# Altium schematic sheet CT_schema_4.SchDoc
size 522 x 483 mm
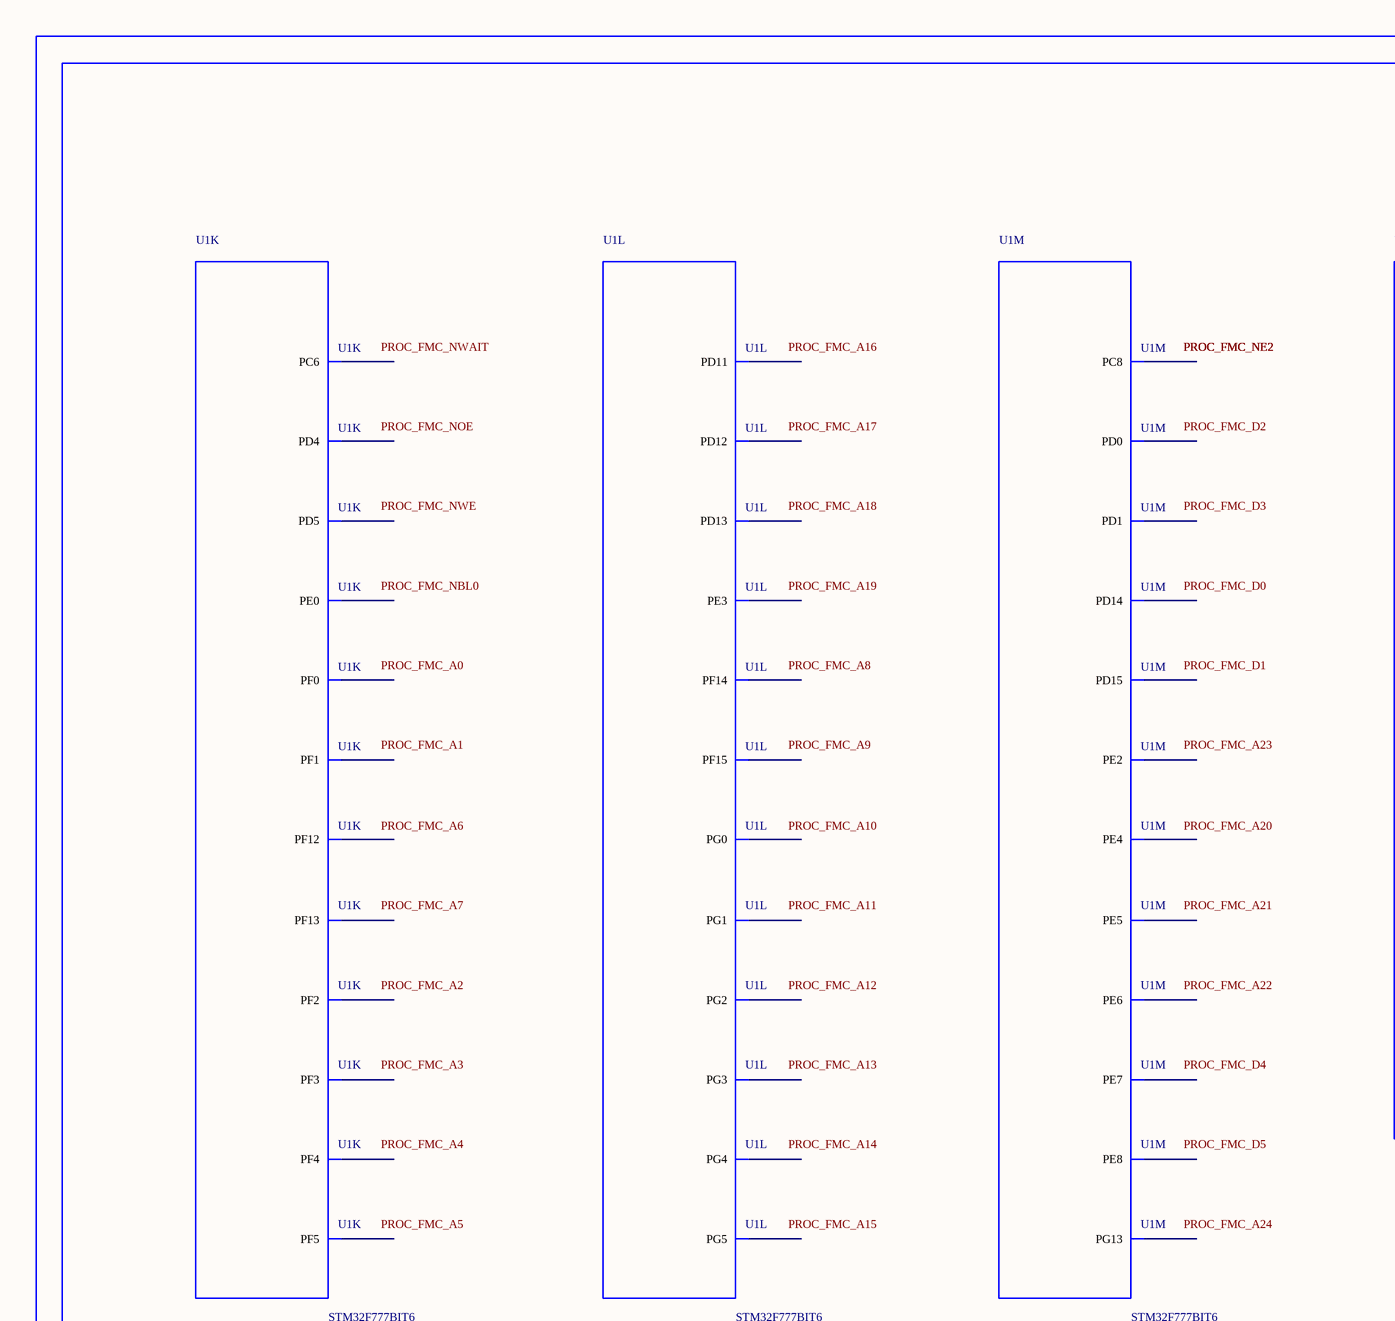
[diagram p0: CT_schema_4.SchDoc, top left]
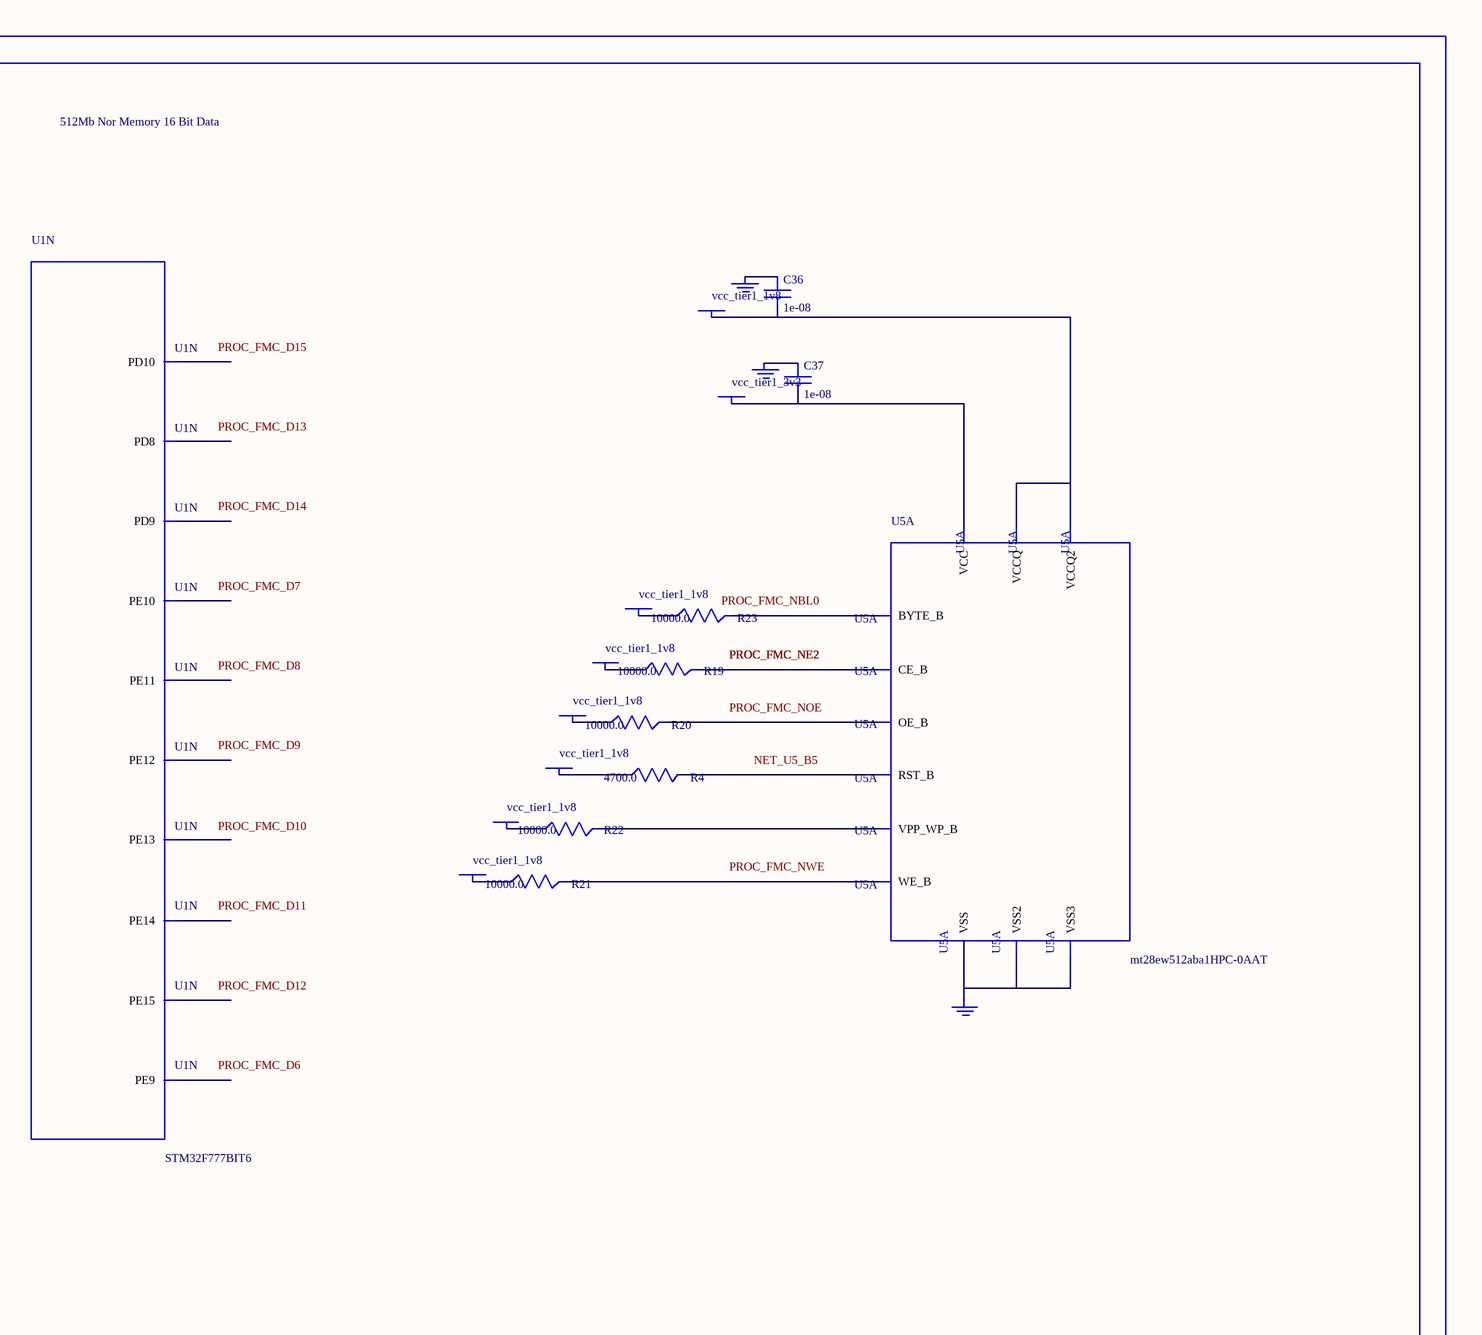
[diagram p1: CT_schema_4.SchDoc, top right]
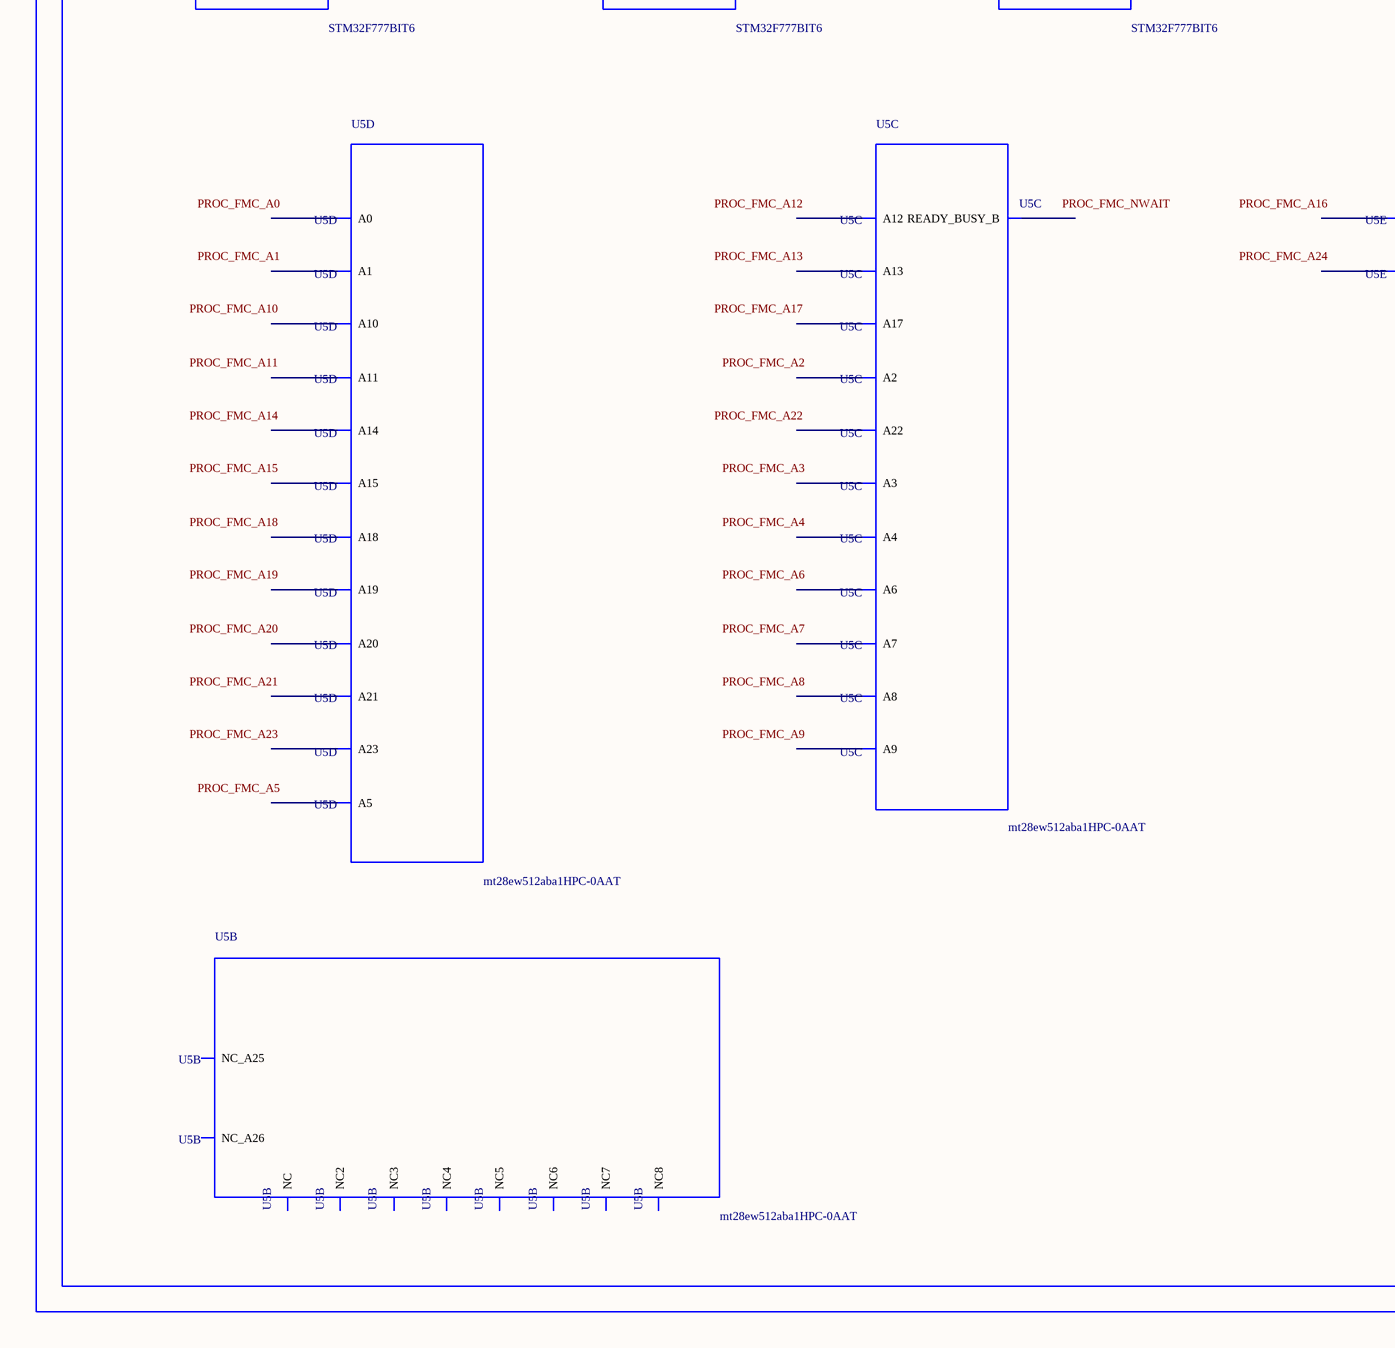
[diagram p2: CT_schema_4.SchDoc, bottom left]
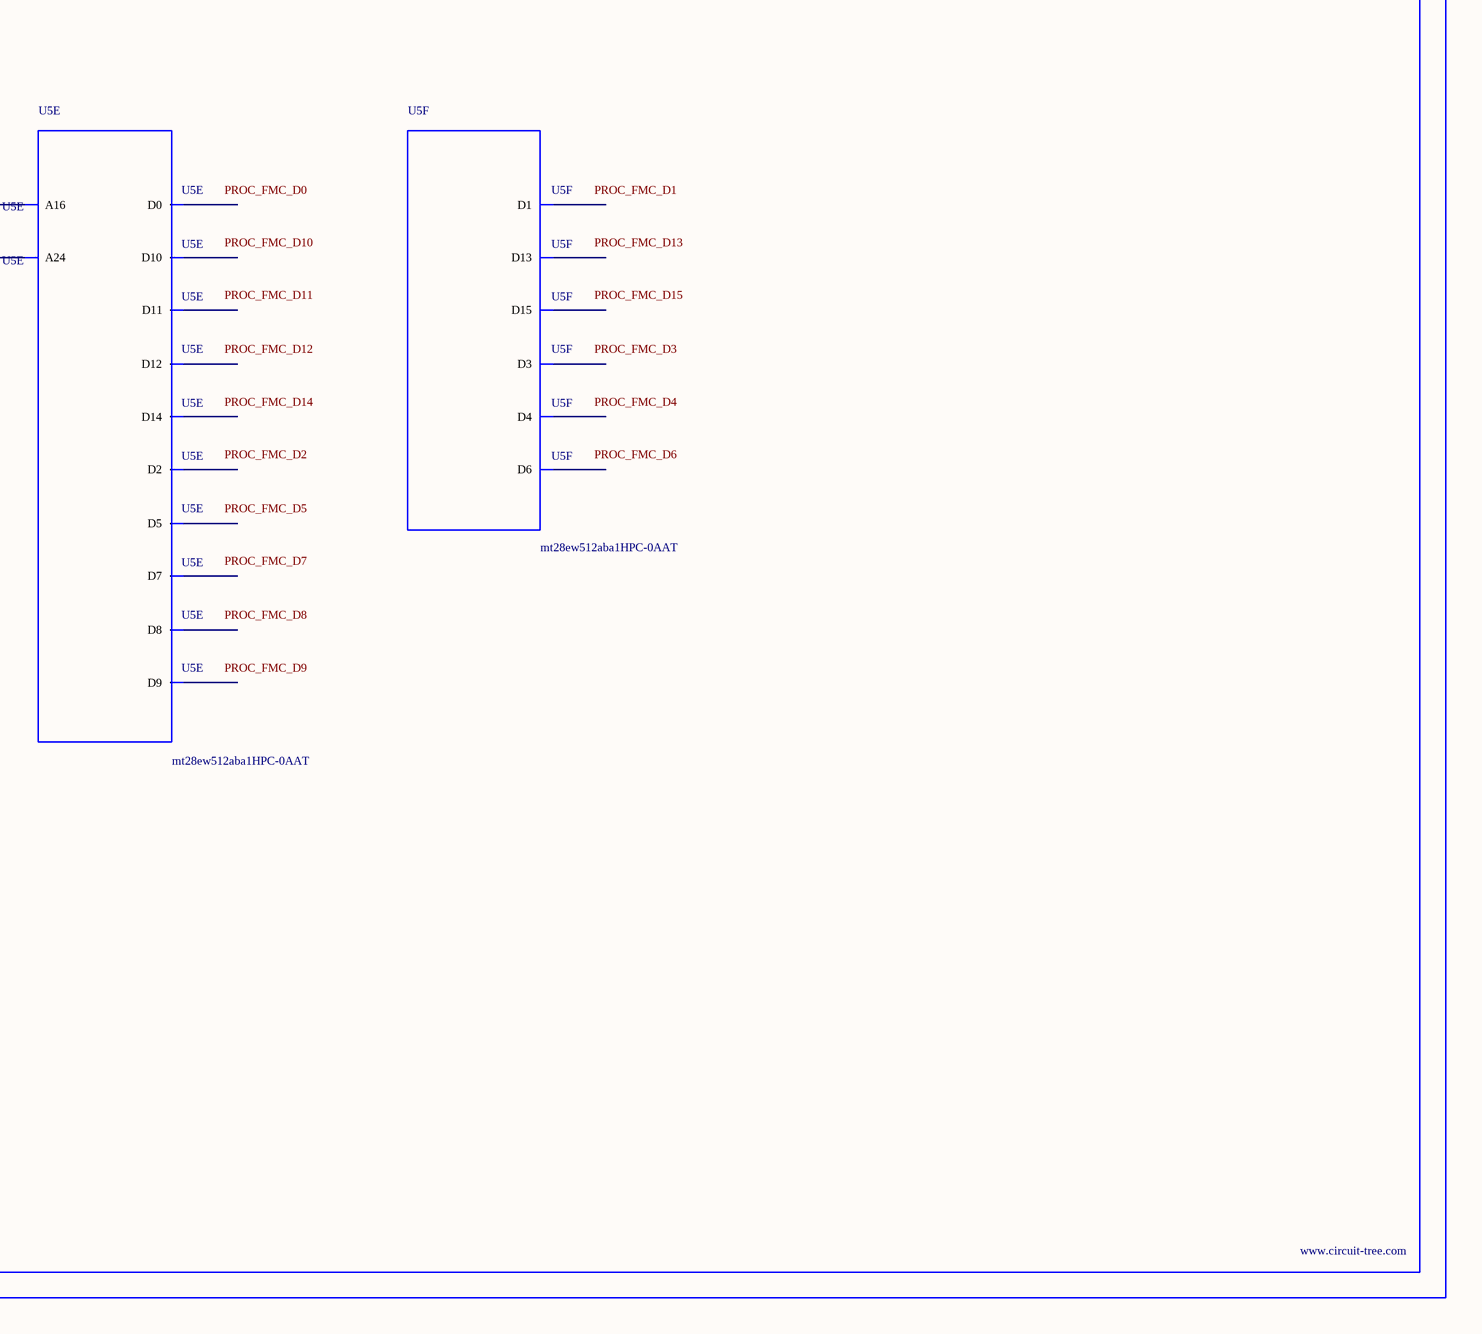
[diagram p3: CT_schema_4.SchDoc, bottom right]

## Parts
BORDER3  (no value)
C36  1e-08  [C0402]
C37  1e-08  [C0402]
GND_INSTANCE_3_0  (no value)
GND_INSTANCE_3_1  (no value)
GND_INSTANCE_3_2  (no value)
POWER_INSTANCE_3_0  vcc_tier1_1v8
POWER_INSTANCE_3_1  vcc_tier1_3v3
POWER_INSTANCE_3_2  vcc_tier1_1v8
POWER_INSTANCE_3_3  vcc_tier1_1v8
POWER_INSTANCE_3_4  vcc_tier1_1v8
POWER_INSTANCE_3_5  vcc_tier1_1v8
POWER_INSTANCE_3_6  vcc_tier1_1v8
POWER_INSTANCE_3_7  vcc_tier1_1v8
R4  4700.0  [R0603]
R19  10000.0  [R0603]
R20  10000.0  [R0603]
R21  10000.0  [R0603]
R22  10000.0  [R0603]
R23  10000.0  [R0603]
U1  STM32F777BIT6  [LQFP208]  (parts K,L,M,N of 15)
U5  mt28ew512aba1HPC-0AAT  [LBGA-64]  (parts A,B,C,D,E,F of 6)

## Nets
NetC36_1: C36.1 GND_INSTANCE_3_0.0(GND)
NetC36_2: C36.2 POWER_INSTANCE_3_0.0(PWR) U5.D8(VCCQ) U5.F1(VCCQ2)
NetC37_1: C37.1 GND_INSTANCE_3_1.0(GND)
NetC37_2: C37.2 POWER_INSTANCE_3_1.0(PWR) U5.G5(VCC)
NetGND_INSTANCE_3_2_0: GND_INSTANCE_3_2.0(GND) U5.E8(VSS) U5.H2(VSS2) U5.H7(VSS3)
NetPOWER_INSTANCE_3_2_0: POWER_INSTANCE_3_2.0(PWR) R19.1
NetPOWER_INSTANCE_3_3_0: POWER_INSTANCE_3_3.0(PWR) R20.1
NetPOWER_INSTANCE_3_4_0: POWER_INSTANCE_3_4.0(PWR) R21.1
NetPOWER_INSTANCE_3_5_0: POWER_INSTANCE_3_5.0(PWR) R22.1
NetPOWER_INSTANCE_3_6_0: POWER_INSTANCE_3_6.0(PWR) R23.1
NetPOWER_INSTANCE_3_7_0: POWER_INSTANCE_3_7.0(PWR) R4.1
NetR4_2: R4.2 U5.B5(RST_B)
NetR19_2: R19.2 U5.F2(CE_B)
NetR20_2: R20.2 U5.G2(OE_B)
NetR21_2: R21.2 U5.A5(WE_B)
NetR22_2: R22.2 U5.B4(VPP_WP_B)
NetR23_2: R23.2 U5.F7(BYTE_B)

Not connected (* = marked no-connect by the designer): U1 1(PE2) 2(PE3) 3(PE4) 4(PE5) 5(PE6) 16(PF0) 17(PF1) 18(PF2) 22(PF3) 23(PF4) 24(PF5) 71(PF12) 74(PF13) 75(PF14) 76(PF15) 77(PG0) 78(PG1) 79(PE7) 80(PE8) 81(PE9) 84(PE10) 85(PE11) 86(PE12) 87(PE13) 88(PE14) 89(PE15) 108(PD8) 109(PD9) 110(PD10) 111(PD11) 112(PD12) 113(PD13) 116(PD14) 117(PD15) 129(PG2) 130(PG3) 131(PG4) 132(PG5) 138(PC6) 140(PC8) 164(PD0) 165(PD1) 168(PD4) 169(PD5) 182(PG13) 200(PE0); U5 A1(NC) A2(A3) A3(A7) A4(READY_BUSY_B) A6(A9) A7(A13) A8(NC2) B1(NC_A26) B2(A4) B3(A17) B6(A8) B7(A12) B8(A22) C1(NC3) C2(A2) C3(A6) C4(A18) C5(A21) C6(A10) C7(A14) C8(A23) D1(NC4) D2(A1) D3(A5) D4(A20) D5(A19) D6(A11) D7(A15) E1(NC5) E2(A0) E3(D0) E4(D2) E5(D5) E6(D7) E7(A16) F3(D8) F4(D10) F5(D12) F6(D14) F8(A24) G1(NC6) G3(D9) G4(D11) G6(D13) G7(D15) G8(NC_A25) H1(NC7) H3(D1) H4(D3) H5(D4) H6(D6) H8(NC8)

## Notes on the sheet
- Labels drawn without touching a wire or pin: NET_U5_B5, PROC_FMC_A0, PROC_FMC_A1, PROC_FMC_A2, PROC_FMC_A3, PROC_FMC_A4, PROC_FMC_A5, PROC_FMC_A6, PROC_FMC_A7, PROC_FMC_A8, PROC_FMC_A9, PROC_FMC_A10, PROC_FMC_A11, PROC_FMC_A12, PROC_FMC_A13, PROC_FMC_A14, PROC_FMC_A15, PROC_FMC_A16, PROC_FMC_A17, PROC_FMC_A18, PROC_FMC_A19, PROC_FMC_A20, PROC_FMC_A21, PROC_FMC_A22, PROC_FMC_A23, PROC_FMC_A24, PROC_FMC_D0, PROC_FMC_D1, PROC_FMC_D2, PROC_FMC_D3, PROC_FMC_D4, PROC_FMC_D5, PROC_FMC_D6, PROC_FMC_D7, PROC_FMC_D8, PROC_FMC_D9, PROC_FMC_D10, PROC_FMC_D11, PROC_FMC_D12, PROC_FMC_D13, PROC_FMC_D14, PROC_FMC_D15, PROC_FMC_NBL0, PROC_FMC_NOE, PROC_FMC_NWAIT, PROC_FMC_NWE

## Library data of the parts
BORDER3 = BORDER_PAGE3
C36 C37 = C0402C103K3RAC
GND_INSTANCE_3_0-GND_INSTANCE_3_2 = GND
POWER_INSTANCE_3_0-POWER_INSTANCE_3_7 = PWR
R4 = RC0603JR-074K7L
R19-R23 = RC0603JR-0710KL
